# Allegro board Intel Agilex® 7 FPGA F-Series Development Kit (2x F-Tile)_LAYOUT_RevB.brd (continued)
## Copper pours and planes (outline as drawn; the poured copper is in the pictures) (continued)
FPGA_VCCPT on BOTTOM: 71.9,50.04 72.83,50.04 73,50.2 73,51.31 72.79,51.51 71.96,51.51 71.69,51.24 71.69,50.25
FPGA_VCCPT on L05_SIG2: 97.29,70.94 105.42,71.07 107.58,72.6 108.47,72.6 114.31,78.44 121.42,78.44 121.67,78.18 122.44,78.18 125.61,75.01 127.77,75.01 131.83,70.94 131.83,69.55 133.61,67.77 133.61,60.02 134.12,59.51 135.26,59.51 137.42,61.67 163.71,61.67 167.01,64.98 167.01,67.9 170.06,70.94 178.82,70.94 179.46,70.31 179.46,63.32 178.32,62.18 173.36,62.18 166.76,55.58 166.76,50.37 165.62,49.23 135.01,49.23 126.88,57.36 126.88,68.28 124.21,70.94 122.82,70.94 122.69,71.07 121.29,71.07 120.91,71.45 120.73,71.45 120.3,71.88 117.53,71.88 116.84,71.19 116.87,66.2 118.52,64.55 118.52,53.53 112.09,49.61 112,49.61 111.13,48.75 111.13,46.69 110.65,46.21 110.65,42.55 111.77,41.43 111.77,31.45 111.13,30.81 97.54,30.81 96.15,32.21 96.15,37.14 95.59,37.7 95.59,40.11 96.53,41.05 96.53,44.86 95.64,45.75 95.64,53.16 96.02,53.55 109.99,53.55 114.69,56.34 114.69,68.28 114.31,68.66 109.61,68.66 109.23,68.28 97.29,68.28 97.04,68.53 97.04,70.69
FPGA_VCCPT on L07_SIG3: 213.11,53.29 213.11,39.45 212.61,38.94 208.29,38.94 207.91,39.32 207.91,47.7 195.46,60.15 174,60.15 170.31,63.83 170.31,72.98 170.82,73.48 179.2,73.48 184.41,68.28 189.75,68.28 190.7,67.33 199.08,67.33
FPGA_VCCPT on L09_PWR1: 99.96,53.16 99.7,53.42 99.19,53.42 98.69,52.91 96.78,52.91 96.27,53.42 96.02,53.42 95.64,53.04 90.3,53.04 88.53,51.26 70.75,51.26 70.49,51.01 70.49,45.04 74.94,40.59 82.05,40.59 85.73,36.91 85.73,28.53 85.99,28.27 92.84,28.27 93.1,28.02 123.96,28.02 133.23,18.75 218.32,18.75 219.46,19.89 219.46,41.23 218.57,42.12 194.95,42.12 193.05,40.21 169.17,40.21 168.28,39.32 168.28,34.75 166.63,33.1 157.11,33.1 156.09,34.11 156.09,68.66 156.85,69.42 182,69.42 182.13,69.55 182.13,89.36 178.82,92.66 149.99,92.66 148.6,91.26 148.6,34.24 148.34,33.99 135.14,33.99 132.6,36.53 109.86,36.53 109.61,36.78 109.61,37.16 109.35,37.42 102.24,37.42 99.96,39.7
FPGA_VCCPT on L12_SIG4: 71.13,51.26 70.49,50.62 58.81,50.62 58.43,51.01 55.51,51.01 48.14,58.37 48.14,61.29 43.31,66.12 43.31,73.48 47.61,77.78 66.45,77.78 68.59,75.64 69.86,75.64 70.24,76.02 70.24,78.69 69.35,79.58 47.38,79.58 41.79,73.99 41.79,66.63 41.28,66.12 41.28,63.2 42.3,62.18 44.71,62.18 46.24,60.66 46.24,53.83 48.88,51.18 50.63,51.18 53.22,48.59 72.14,48.59 72.78,49.23 72.78,51.13 72.65,51.26
FPGA_VCCPT on L12_SIG4: 170.82,73.87 179.08,73.87 182.89,70.06 194.95,70.06 200.71,64.3 200.71,56.3 214.38,42.62 214.38,39.7 213.75,39.07 211.59,39.07 207.65,43 205.11,43 190.76,57.36 181.11,57.36 172.22,66.25 170.31,66.25 169.17,67.39 169.17,72.21
FPGA_VCCPT on L16_SIG6: 107.45,70.94 107.7,70.69 107.7,69.42 103,64.72 103,53.16 102.62,52.78 99.19,52.78 98.81,53.16 98.81,66.12 97.29,67.64 97.29,70.56 97.67,70.94
FPGA_VCCR_CORE on TOP (solid shape): 49.41,74.88 49.41,72.47 49.16,72.21 48.65,72.21 48.27,71.83 48.27,66.25 48.01,65.99 42.43,65.99 42.17,66.25 42.17,74.25 42.43,74.5 43.95,74.5 44.53,75.09 49.21,75.09
FPGA_VCCR_CORE on BOTTOM (solid shape): 47.63,74.12 47.63,71.83 47.51,71.71 47.51,68.02 47.63,67.9 47.63,66.5 47.38,66.25 42.17,66.25 41.66,66.75 41.66,71.2 42.68,72.21 42.68,74.25 42.81,74.37 47.38,74.37
FPGA_VCCR_CORE on TOP: 77.93,29.68 81.8,29.68 81.92,29.81 81.92,32.8 81.8,32.92 77.92,32.92 77.67,32.67 77.67,29.93
FPGA_VCCR_CORE on L09_PWR1: 63.25,28.27 84.84,28.27 85.35,28.78 85.35,36.65 81.92,40.08 74.94,40.08 70.11,44.91 70.11,51.01 69.86,51.26 59.44,51.26 55.63,55.07 55.63,64.85 53.98,66.5 53.98,81.61 53.6,81.99 39.38,81.99 39,81.61 39,76.02 35.57,72.6 35.57,55.96
FPGA_VCCR_CORE on L12_SIG4: 47.78,77.32 66.15,77.32 70.62,72.85 72.78,72.85 73.81,71.82 74.7,71.82 75.24,71.28 77.58,71.28 79.36,70.18 80.74,70.18 85.35,67.52 85.61,67.26 86.11,67.26 86.37,67.52 86.88,67.52 87.13,67.26 87.34,67.26 92.09,70.06 101.66,70.06 101.91,69.8 102.6,69.8 103.54,68.86 104.81,68.86 105.75,69.8 106.18,69.8 106.43,70.06 109.1,70.06 109.35,69.8 109.35,66.57 105.42,64.41 105.42,56.21 106.94,54.69 107.32,54.69 107.83,54.18 107.83,50.75 104.91,47.83 87,47.83 86.11,46.94 83.32,46.94 82.94,46.56 80.78,46.56 80.65,46.69 79.76,46.69 79.51,46.43 76.21,46.43 74.43,48.21 74.05,48.21 73.16,49.1 73.16,51.26 72.78,51.64 71,51.64 70.37,51.01 59.06,51.01 58.55,51.51 55.63,51.51 48.65,58.5 48.65,61.55 43.7,66.5 43.7,73.23
LTC_VDD33 on TOP: 233.94,28.65 231.27,28.65 231.02,28.91 231.02,30.43 231.27,30.69 233.94,30.69 234.2,30.43 234.2,28.91
LTC_VDD33 on BOTTOM: 172.22,57.99 170.95,57.99 170.7,58.24 170.7,62.44 170.95,62.69 179.59,62.69 179.84,62.44 179.84,60.66 179.59,60.4 176.28,60.4 176.03,60.66 175.39,60.66 174.76,61.29 172.73,61.29 172.47,61.04 172.47,58.24
LTC_VDD33 on L16_SIG6: 196.22,38.43 195.33,39.32 195.33,42.88 194.57,43.64 188.6,43.64 185.94,46.31 185.94,48.85 186.19,49.1 186.57,49.1 187.08,48.59 187.08,47.45 187.59,47.45 187.84,47.7 187.84,52.02 184.28,55.58 184.28,58.75 181.24,61.8 172.22,61.8 171.33,60.91 171.33,54.05 178.06,47.32 178.06,42.37 189.75,30.69 212.86,30.69 217.43,26.11 234.32,26.11 235.08,26.88 235.08,30.81 234.32,31.57 222,31.57 215.15,38.43
MAX_1V2 on BOTTOM (solid shape): 17.68,70.99 18.6,70.99 18.8,70.79 18.8,65.61 17.41,64.21 16.71,64.21 16.63,64.23 15.9,64.23 15.9,64.47 16.62,64.47 16.62,64.75 15.89,64.75 15.89,65.36 16.39,65.86 16.39,70.46 17.1,70.46 17.1,70.84 16.72,70.84 16.72,70.46 16.39,70.46 16.39,71.2 17.48,71.2
MAX_1V2 on BOTTOM: 20.71,85.68 20.71,84.53 20.84,84.41 21.34,84.41 21.44,84.51 21.44,85.78 20.81,85.78
MAX_1V2 on L16_SIG6: 16.01,67.26 16.01,81.61 19.44,85.04 20.45,85.04 21.09,85.68 27.06,85.68 29.73,83.01 29.73,76.28 30.49,75.52 31.25,75.52 31.63,75.14 31.63,73.48 31.12,72.98 26.17,72.98 25.41,72.21 25.41,70.94 21.11,66.65 16.62,66.65
MAX_1V8 on BOTTOM (solid shape): 33.64,101.8 33.68,101.79 34.31,101.79 34.41,101.69 34.41,101.55 33.69,101.55 33.69,101.27 34.42,101.27 34.42,99.78 35.44,98.76 35.44,94.57 35.31,94.44 34.04,94.44 33.79,94.69 33.79,98 32.9,98.88 32.9,100.81 32.94,100.81 33.17,100.93 33.26,101.16 33.23,101.3 33.15,101.42 33.53,101.81 33.6,101.81
MAX_1V8 on BOTTOM: 25.41,55.07 27.19,55.07 28.07,54.18 28.07,52.15 27.95,52.02 27.06,52.02 26.93,52.15 26.93,53.16 26.55,53.55 25.41,53.55 ; 1 cut-out
MAX_1V8 on L03_SIG1: 34.63,95.2 36.74,95.2 37.5,95.96 38.11,95.96 38.12,95.95 38.2,95.95 39.35,97.11 42.17,97.11 42.68,97.61 67.01,97.61 67.19,97.44 67.19,95.33 64.88,93.02 64.88,83.11 69.53,78.46 72.6,78.46 72.88,78.74 72.88,79.58 72.55,79.91 70.54,79.91 66.66,83.8 66.66,92.05 69.53,94.92 69.53,98.88 67.85,100.56 43.19,100.56 42.15,99.52 39.05,99.52 36.6,97.07 35.02,97.07 34.49,96.54 34.49,95.34
MAX_1V8 on L09_PWR1: 38.49,94.19 35.82,96.85 32.9,96.85 29.85,93.8 23.76,93.8 22.74,92.79 22.74,85.42 22.87,85.3 23.38,85.3 24.65,86.57 28.33,86.57 29.34,85.55 29.34,82.88 27.44,80.98 27.19,80.98 26.93,80.72 26.93,80.09 26.55,79.71 25.79,79.71 25.41,80.09 25.41,80.72 25.03,81.1 23.88,81.1 23.38,80.6 23.38,76.66 21.72,75.01 21.72,73.61 22.87,72.47 29.98,72.47 30.49,71.96 30.49,62.56 29.22,61.29 17.15,61.29 16.9,61.04 16.9,56.34 19.82,53.42 29.73,53.42 32.39,56.09 34.93,56.09 35.19,56.34 35.19,72.85 38.49,76.15
MAX_2V5 on TOP (solid shape): 33.92,99.9 33.92,98.88 34.3,98.5 34.3,94.57 34.04,94.31 33.15,94.31 32.9,94.57 32.9,98.38 32.39,98.88 32.39,99.75 33.13,99.75 33.13,100.03 32.39,100.03 32.39,100.15 32.51,100.27 33.14,100.27 33.17,100.27 33.22,100.28 33.54,100.28
MAX_2V5 on BOTTOM: 32.77,94.31 33.28,94.31 33.54,94.57 33.54,96.73 33.28,96.98 32.77,96.98 32.52,96.73 32.52,94.57
MAX_2V5 on L10_PWR2: 38.49,94.19 35.82,96.85 32.9,96.85 29.85,93.8 23.76,93.8 22.74,92.79 22.74,85.42 22.87,85.3 23.38,85.3 24.65,86.57 28.33,86.57 29.34,85.55 29.34,82.88 27.44,80.98 27.19,80.98 26.93,80.72 26.93,80.09 26.55,79.71 25.79,79.71 25.41,80.09 25.41,80.72 25.03,81.1 23.88,81.1 23.38,80.6 23.38,76.66 21.72,75.01 21.72,73.61 22.87,72.47 33.15,72.47 35.06,74.37 35.06,75.77 38.49,79.2
MAX_VCCD on L03_SIG1: 22.08,85.45 25.51,85.45 26.68,84.28 31.38,84.28 31.76,83.9 31.76,79.33 31.5,79.07 30.11,79.07 29.73,78.69 29.73,72.72 30.23,72.21 31.25,72.21 31.63,71.83 31.63,69.29 31.25,68.91 20.84,68.91 20.45,69.29 20.45,83.82
PCIE_3V3_AUX on TOP: 54.35,5.8 53.98,6.17 53.98,8.46 54.24,8.71 54.87,8.71 55.13,8.46 55.13,5.92 54.95,5.75 54.95,2.6 54.35,2.6
PCIE_3V3_AUX on BOTTOM: 54.24,7.19 54.87,7.19 55.13,7.44 55.13,8.84 55,8.97 54.11,8.97 53.98,8.84 53.98,7.44
PCIE_3V3_AUX on L16_SIG6: 54.62,5.67 52.08,5.67 44.03,13.72 38.18,13.72 33.99,17.91 33.99,26.16 34.07,26.24 34.55,26.24 35.47,25.33 39.66,25.33 47.06,17.92 47.06,14.49 47.76,13.79 51.89,13.79 53.51,12.18 55.2,12.18 56.02,11.36 56.02,9.01 55.43,8.42 55.43,6.48
PCIE_EP_3V3 on TOP: 52.35,2.6 52.35,5.77 52.08,6.05 52.08,8.59 52.2,8.71 53.22,8.71 53.35,8.59 53.35,6.17 52.95,5.78 52.95,2.6
PCIE_EP_3V3 on BOTTOM: 53.35,2.6 53.35,5.66 52.08,6.94 52.08,8.77 52.25,8.94 53.5,8.94 53.73,8.71 53.73,7.32 54.95,6.09 54.95,2.6
PCIE_EP_3V3 on L03_SIG1: 54.87,11.51 54.87,10.75 53.86,9.73 53.86,6.3 53.6,6.05 52.08,6.05 51.82,6.3 51.82,9.73 51.19,10.37 49.54,10.37 49.16,10.75 49.16,11.51 49.54,11.89 54.49,11.89
PCIE_EP_12V on TOP: 45.65,6 45.65,8.89 46.08,9.32 48.65,9.32 48.93,9.05 48.93,6.96 48.7,6.73 48.52,6.73 48.22,6.43 48.22,5.92 47.95,5.66 47.95,2.6 45.45,2.6 45.45,5.79
PCIE_EP_12V on TOP: 226.96,44.02 226.58,43.64 220.48,43.64 220.1,43.26 220.1,31.83 220.61,31.32 226.58,31.32 227.21,31.96 227.21,39.45 227.08,39.58 227.08,40.22 226.93,40.38 226.93,41.33 227.08,41.48 227.08,44.02 ; 1 cut-out
PCIE_EP_12V on BOTTOM: 219.97,31.32 226.96,31.32 227.21,31.57 227.21,40.72 226.96,40.97 226.96,43.39 226.7,43.64 219.97,43.64 219.72,43.39 219.72,31.57
PCIE_EP_12V on BOTTOM: 46.35,2.6 46.35,5.8 46.11,6.05 46.11,8.82 46.26,8.97 48.52,8.97 48.65,8.84 48.65,6.81 48.22,6.38 48.22,5.92 47.95,5.66 47.95,2.6
PCIE_EP_12V on L09_PWR1: 46.27,5.92 46.27,10.92 46.26,11.16 46.24,11.4 46.24,11.51 49.79,15.06 62.49,15.06 65.67,11.89 121.29,11.89 124.59,15.19 129.67,15.19 132.47,17.99 138.06,17.99 138.44,17.99 218.7,17.99 220.23,19.51 220.23,43.13 220.86,43.77 228.23,43.77 228.73,43.26 228.73,15.06 227.72,14.05 169.93,14.05 169.93,14.02 140.78,14.02 138.64,13.14 137.76,11 137.76,10.26 130.66,10.26 128.8,9.48 128.03,7.62 128.03,6.3 59.37,6.3 59.37,7.45 57.15,9.67 54.93,7.45 54.93,6.17 54.55,5.79 46.4,5.79
PCIE_EP_12V on L10_PWR2: 46.27,5.92 46.27,10.92 46.26,11.16 46.24,11.4 46.24,11.51 49.79,15.06 62.49,15.06 65.67,11.89 121.29,11.89 124.59,15.19 129.67,15.19 132.47,17.99 218.7,17.99 220.23,19.51 220.23,43.13 220.86,43.77 228.23,43.77 228.73,43.26 228.73,15.06 227.72,14.05 169.93,14.05 169.93,14.02 140.78,14.02 138.64,13.14 137.76,11 137.76,10.26 130.66,10.26 128.8,9.48 128.03,7.62 128.03,6.3 59.37,6.3 59.37,7.45 57.15,9.67 54.93,7.45 54.93,6.17 54.55,5.79 46.4,5.79
PCIE_VDD_1V85 on TOP (solid shape): 231.02,46.31 230.39,46.31 229.88,45.8 229.88,45.42 229.75,45.29 229.12,45.29 228.99,45.42 228.99,45.8 230.26,47.07 230.26,47.7 230.39,47.83 231.02,47.83
QSFP_VCC on BOTTOM (solid shape): outline of 922 points within 36.99,49.1 48.75,58.27
QSFP_VCCR on BOTTOM (solid shape): outline of 100 points within 36.99,47.27 45.5,49.46
QSFP_VCCT on BOTTOM (solid shape): outline of 828 points within 36.98,40.31 48.7,48.82
QSFPDD_VCC on BOTTOM (solid shape): outline of 236 points within 48.14,27.41 58.81,35.28
QSFPDD_VCCR on BOTTOM (solid shape): 49.43,27.7 49.66,27.47 52.52,27.47 52.84,27.16 52.84,26.39 52.59,26.14 48.01,26.14 48.01,29.33 48.05,29.33 48.05,31.58 49.43,31.58
QSFPDD_VCCT on BOTTOM (solid shape): outline of 168 points within 48.06,22.3 59.32,27.03
SW0 on TOP: 153.42,41.73 153.3,41.61 153.3,40.08 153.42,39.96 154.82,39.96 155.07,39.7 155.07,36.65 155,36.58 150.2,36.58 149.41,37.37 149.41,44.33 150.22,45.14 154.97,45.14 155.07,45.04 155.07,41.73
SW1 on TOP: 153.42,27.13 153.3,27 153.3,25.48 153.42,25.35 154.82,25.35 155.07,25.1 155.07,22.18 154.95,22.05 149.84,22.05 149.41,22.48 149.41,30.18 149.77,30.53 154.97,30.53 155.07,30.43 155.07,27.13
SW2 on TOP: 153.42,56.21 153.3,56.09 153.3,54.56 153.42,54.43 154.82,54.43 155.07,54.18 155.07,51.13 155,51.06 150.12,51.06 149.41,51.77 149.41,58.88 150.15,59.62 154.97,59.62 155.07,59.51 155.07,56.21
SW3 on TOP: 153.42,70.69 153.3,70.56 153.3,69.04 153.42,68.91 154.57,68.91 154.82,68.66 154.82,65.61 154.74,65.53 150.12,65.53 149.41,66.25 149.41,73.36 150.15,74.09 154.97,74.09 155.07,73.99 155.07,70.69
SW4 on TOP: 153.42,85.17 153.3,85.04 153.3,83.52 153.42,83.39 154.82,83.39 155.07,83.14 155.07,80.09 155,80.01 150.12,80.01 149.41,80.72 149.41,87.84 150.15,88.57 154.97,88.57 155.07,88.47 155.07,85.17
U93_AGND on TOP (solid shape): outline of 824 points within 39.38,87.58 52.2,94.06
U93_AGND on BOTTOM (solid shape): outline of 252 points within 38.74,75.42 51.44,94.57
U93_AGND on TOP: 51.72,89.08 51.72,89.99 51.59,90.12 48.22,90.12 48.09,89.99 48.09,89.03 48.22,88.9 48.5,88.9 48.8,88.6 48.8,88.22 48.9,88.12 49.13,88.12 49.21,88.19 49.21,88.6 49.51,88.9 51.54,88.9
U93_AGND on L14_SIG5: 51.34,89.39 51.34,91.85 52.2,92.71 52.2,93.3 51.82,93.68 47.38,93.68 46.74,93.04 46.24,93.04 45.6,92.41 45.6,91.8 43.54,89.74 42.35,89.74 41.87,89.26 39.94,89.26 39.55,88.88 39.55,87.68 39.83,87.4 46.67,87.4 48.32,89.06 51.01,89.06
U93_VDD25 on L03_SIG1: 39.22,92.33 39.22,89.06 39.53,88.75 41.31,88.75 42.35,89.79 42.35,92.23 41.61,92.97 39.86,92.97
U93_VDD25 on L05_SIG2: 46.87,93.93 42.04,93.93 41.03,92.92 41.03,89.99 43.95,87.07 47.51,87.07 48.14,87.71 48.14,88.72 47.63,89.23 47.63,93.17
U93_VDD33 on L03_SIG1: 43.82,93.68 46.95,93.68 47.3,93.32 47.3,91.57 47.48,91.39 48.78,91.39 49.11,91.06 49.11,90.17 49.79,89.49 49.79,87.71 49.41,87.33 42.09,87.33 41.64,87.79 41.64,88.5 43.2,90.06 43.2,93.06
U96_AGND on TOP (solid shape): outline of 813 points within 195.23,75.52 201.81,88.72
U96_AGND on TOP: 196.83,76.38 197.75,76.38 197.87,76.51 197.87,79.89 197.75,80.01 196.78,80.01 196.65,79.89 196.65,79.61 196.35,79.3 195.97,79.3 195.87,79.2 195.87,78.97 195.94,78.9 196.35,78.9 196.65,78.59 196.65,76.56
U96_AGND on BOTTOM: 196.93,79.13 197.05,79.01 197.05,76.66 197.49,76.66 197.75,76.91 197.75,79.62 197.58,79.78 195.29,79.78 195.02,80.06 195.02,83.33 195.33,83.64 195.33,84.41 195.46,84.53 201.56,84.53 201.68,84.41 201.68,79.45 201.81,79.33 202.06,79.33 202.32,79.58 202.32,88.6 201.43,89.49 187.97,89.49 187.33,90.12 183.75,90.12 183.65,90.02 183.65,89.23 183.67,89.21 183.67,88.29 184.08,87.89 193.89,87.89 194.32,87.45 194.32,84.41 193.94,84.03 193.94,80.18 194.99,79.13 ; 2 cut-outs
U96_VDD25 on L16_SIG6: 202.06,88.47 202.06,85.68 201.68,85.3 199.4,85.3 199.02,84.91 199.02,83.77 197.75,82.5 197.75,80.09 197.37,79.71 195.46,79.71 195.08,80.09 195.08,83.39 196.48,84.79 196.48,88.47 196.86,88.85 201.68,88.85
U96_VDD33 on L16_SIG6: 198.13,82.25 198.13,79.83 197.62,79.33 195.21,79.33 194.7,79.83 194.7,83.64 196.1,85.04 196.1,86.44 195.71,86.82 193.17,86.82 192.79,86.44 192.79,76.66 193.05,76.41 200.92,76.41 202.06,77.55 202.06,84.53 201.68,84.91 199.78,84.91 199.4,84.53 199.4,83.52
ZL30733_1V8 on TOP (solid shape): 69.22,64.47 69.22,63.45 66.68,63.45 66.18,62.95 65,62.95 65,63.68 64.78,63.68 64.78,63.07 64.54,63.07 64.54,63.69 64.53,63.72 64.52,63.77 64.52,64.34 64.65,64.47 66.05,64.47 66.3,64.72 68.97,64.72
ZL30733_1V8 on BOTTOM (solid shape): outline of 243 points within 59.19,58.75 72.02,65.48
ZL30733_1V8 on BOTTOM: 57.54,43.77 57.54,44.78 55.23,44.78 55.05,44.61 55.05,43.39 55.18,43.26 55.63,43.26 56.14,43.77
ZL30733_1V8 on L14_SIG5: 58.6,60.66 60.71,60.66 60.97,60.4 60.97,59.72 60.38,59.13 60.38,46.87 56.65,43.13 55.25,43.13 55.18,43.21 55.18,43.87 57.54,46.23 57.54,46.74 58.33,47.53 58.33,60.38
N93250 on BOTTOM: 52.11,94.82 52.11,99.16 51.9,99.37 49.97,99.37 49.82,99.22 49.82,94.82 49.99,94.64 50.66,94.64 50.84,94.82
N632203 on L16_SIG6: 6.61,55.83 6.61,47.58 6.87,47.32 13.6,47.32 13.85,47.58 13.85,55.83 13.6,56.09 6.87,56.09
N632667 on L07_SIG3: 12.71,52.28 12.71,50.37 12.45,50.12 2.67,50.12 2.42,50.37 2.42,52.28 2.67,52.53 12.45,52.53
N757891 on TOP: 246.74,109.43 247.83,109.96 249.03,110.14 251.86,108.97 253.03,106.14 253.02,105.87 252.99,105.6 252.99,99.9 252.77,99.36 252.23,99.14 251.47,99.14 251.2,99.03 251.09,98.76 251.09,96.98 251.2,96.71 251.47,96.6 252.23,96.6 252.77,96.38 252.99,95.84 252.99,16.99 253,16.82 253.01,16.65 252.73,15.18 251.93,13.92 246.08,13.92 245.28,15.18 245,16.65 246.18,19.48 249.01,20.65 250.43,20.39 251.67,19.64 252.1,19.64 252.37,19.75 252.48,20.02 252.48,95.71 252.37,95.98 252.1,96.09 251.34,96.09 250.8,96.31 250.58,96.85 250.58,98.88 250.8,99.42 251.34,99.65 252.1,99.65 252.37,99.76 252.48,100.03 252.48,102.44 252.37,102.71 252.1,102.82 251.26,102.82 251.05,102.69 250.84,102.58 249.96,102.25 249.03,102.14 247.77,102.34 246.64,102.93 245.03,106.14 246.64,109.35 246.64,109.43
N757891 on BOTTOM: 246.74,109.43 247.83,109.96 249.03,110.14 251.86,108.97 253.03,106.14 253.02,105.87 252.99,105.6 252.99,99.9 252.77,99.36 252.23,99.14 251.47,99.14 251.2,99.03 251.09,98.76 251.09,96.98 251.2,96.71 251.47,96.6 252.23,96.6 252.77,96.38 252.99,95.84 252.99,16.99 253,16.82 253.01,16.65 252.73,15.18 251.93,13.92 246.08,13.92 245.28,15.18 245,16.65 246.18,19.48 249.01,20.65 250.43,20.39 251.67,19.64 252.1,19.64 252.37,19.75 252.48,20.02 252.48,95.71 252.37,95.98 252.1,96.09 251.34,96.09 250.8,96.31 250.58,96.85 250.58,98.88 250.8,99.42 251.34,99.65 252.1,99.65 252.37,99.76 252.48,100.03 252.48,102.19 252.33,102.55 251.98,102.69 251.06,102.69 250.08,102.28 249.03,102.14 246.7,102.89 245.24,104.85 242.96,104.85 242.83,104.98 242.83,108.92 243.34,109.43 ; 3 cut-outs
N1703797 on BOTTOM: 71.25,44.91 71.51,44.66 72.78,44.66 72.91,44.78 72.91,48.59 71.41,50.09 71.41,54.36 71.28,54.49 70.77,54.49 70.65,54.36 70.65,48.03 70.8,47.88 71.05,47.88 71.25,47.68 ; 2 cut-outs
N2608710 on TOP: 240.62,25.53 240.62,27.97 240.09,28.5 238.21,28.5 236.13,26.42 231.32,26.42 231.02,26.11 231.02,24.46 231.27,24.21 239.3,24.21
N2975570 on BOTTOM: 52.11,102.44 52.11,106.78 51.9,106.99 49.97,106.99 49.82,106.84 49.82,105.74 50.55,105.01 50.55,104.22 49.82,103.49 49.82,102.39 49.97,102.24 50.98,102.24 51.19,102.44
N6231213 on TOP (solid shape): 50.12,82.04 50.12,79.91 49.54,79.33 49.54,77.19 49.41,77.07 44.51,77.07 44.51,81.87 44.76,82.12 50.05,82.12
N6231502 on TOP (solid shape): 56.09,80.77 56.09,77.07 51.32,77.07 51.19,77.19 51.19,79.2 50.48,79.91 50.48,82.04 50.55,82.12 54.74,82.12
N6646840 on TOP (solid shape): 189.87,77.55 189.87,72.6 189.36,72.09 184.03,72.09 183.78,72.34 183.78,76.36 183.78,76.66 184.03,76.91 186.72,76.91 187.43,77.63 189.8,77.63
N6648304 on TOP (solid shape): 189.87,84.41 189.87,78.06 189.75,77.93 187.46,77.93 186.82,78.56 183.78,78.56 183.61,78.73 183.61,84.49 184.03,84.91 189.36,84.91
N6731924 on TOP: 71.76,42.24 72.57,42.24 72.57,38.35 72.14,37.92 66.05,37.92 65.03,36.91 65.03,35 63.76,35 63.76,38.69 64.52,39.45 71,39.45 71.76,40.21 ; 10 cut-outs
N8086837 on BOTTOM: 223.91,64.85 223.91,66.88 223.53,67.26 220.61,67.26 220.48,67.13 220.48,66.25 220.61,66.12 222.38,66.12 222.89,65.61 222.89,64.85

Small or netless copper shapes (teardrops, artwork), in the pictures only: 97 on TOP, 35 on BOTTOM

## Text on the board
BOTTOM: 100-0330678-B1 RevB1 | BOTTOM SIDE LAYER 18
User.Comments: CR_111111_33 | CR_111111_31 | CR_111111_29 | CR_111111_28 | CR_UNNAMED_68 | CR_111111_30 | CR_111111_22 | CR_1_6 | CR_123_1 | CR_111111_18 | CR_111111_19 | CR_UNNAMED_45 | CR_111111_24 | CR_111111_17 | CR_111111_25 | CR_111111_23 | CR_111111_27 | CR_111111_21 | CR_111111_26 | CR_111111_20 | CR_UNNAMED_27 | CR_U34_2 | CR_UNNAMED_48 | CR_UNNAMED_38 | CR_111111_1 | CR_UNNAMED_31 | CR_UNNAMED_32 | CR_UNNAMED_28 | CR_UNNAMED_36 | CR_111111_2 | CR_111111_3 | CR_111111_4 | CR_U32_2 | CR_U32_1 | CR_4444_1 | CR_11_2 | CR_UNNAMED_56 | CR_UNNAMED_49 | CR_UNNAMED_23 | CR_Q4_3 | CR_U69_1 | CR_U17_1 | CR_654321_5 | CR_Q4_2 | CR_UNNAMED_30 | CR_UNNAMED_26 | CR_654321_4 | CR_123456_19 | CR_123456_52 | CR_123456_54 | CR_123456_8 | CR_1123_2 | CR_123456_56 | CR_123456_17 | CR_1111111_2 | CR_1111111_4 | CR_1111111_5 | CR_1111111_7 | CR_Q4_5 | CR_1111111_6 | CR_UNNAMED_74 | CR_1111111_9 | CR_1111111_10 | CR_1111111_1 | CR_123456_39 | CR_UNNAMED_53 | CR_UNNAMED_63 | CR_111111_32 | CR_41_2 | CR_41_3 | CR_123456_40 | CR_111111_59 | CR_111111_58 | CR_111111_55 | CR_111111_56 | CR_111111_57 | CR_111111_54 | CR_1111_2 | CR_111111_10 | CR_111111_11 | CR_111111_9 | CR_111111_12 | CR_111111_5 | CR_UNNAMED_77 | CR_UNNAMED_78 | CR_UNNAMED_79 | CR_111111_6 | CR_111111_8 | CR_111111_7 | CR_111111_35 | CR_111111_36 | CR_444444_2 | CR_UNNAMED_69 | CR_Q4_4 | CR_Q4_6 | MEZZANINE MODULE | NOTES: UNLESS OTHERWISE SPECIFIED | 1.  ASSEMBLY BOARD PER IPC-A-610 (LATEST REVISION) STANDARD. | 2.  HANDLE MOISTURE SENSITIVE DEVICES(MSD) PER MANUFACTURE'S | CALL OUT ON MSD LABEL.  IF MSD LABEL IS MISSING OR NOT LEGIBLE | 3.  USE IPC-7711/7721 (LATEST REVISION) FOR ALL PCBA REWORK. | THEN ALL PLASTIC PACKAGED COMPONENTS ARE TO BE CONSIDERED MSD | LEVEL 6 AND USE EIA/JEP 113-A FOR HANDLING.
TOP: TOP SIDE LAYER 1
Ref Des/Silkscreen Top: EXTERNAL JTAG | TCK | TDO | TMS | TDI | CFG1 | CFG0 | IMG_SEL1 | D12:FPGA_CONF_DONE | D5:OVERTEMP | QSFP | 1 | 2 | D1:MAX_CONF_DONE | D2:POWER GOOD | IMG_SEL0 | QSFPDD | LTC7132 PROG | MAX10_JTAG_EN | CPU_RESETn | HPS_RESETN | Config Mode | AS x4 Norm | AS x4 Fast | AVST x16 | JTAG | (CVP) | PCIE_PERSTn | GXF_2ND_PERSTN | MSEL2 | 0 | CXL_PERSTn | MSEL1 | SW3 | MSEL0 | 3 | CLOSE-->SELECT | OPEN-->DESELECT | CLOSE=0 | OPEN=1 | MAX_I2C | USB_MAX_JTAG_SEL | CLOSED=0.5% DOWN SPREAD | LTC3888 PROG | OPEN=NO SREAD SPECTRUM | SW4.1 | SW4.2 TO SW4.4 | OPEN=HIGH | PCIE PRESENT | CLOSED=LOW | X16 | X4 | X8 | X1 | SCL | 1_PPS_SCOPE1 | POWER_ON | SDA | 1_PPS_SCOPE2 | CXL | A | DDR4 DIMM 2 | DDR4 DIMM 1 | HPS_GPIO | USER LEDS | INPUT POWER | FAN | Agilex F-Series FPGA Development Kit, Two F-Tile Edition | 2LI
DIMENSION: 3X | 59.6 | 0.1339 | 0.0340 | 0.0551 | 0.0681 | 0.1585 | 0.2521 | 3.40 | 0.86 | 1.40 | 1.73 | 4.03 | 6.40 | 45 X.0200 | 45 X0.51 | 2X | 3.65 | 0.1437 | 1.9 | .0748 | 2.74 | .1080 | 3.51 | .1380
PAGE_OUTLINE: THIS DOCUMENT CONTAINS PROPRIETARY INFORMATION | OF INTEL CORP. NEITHER THE DOCUMENT NOR SAID | PROPRIETARY INFORMATION SHALL BE PUBLISHED, | REPRODUCED, COPIED, DISCLOSED OR USED FOR ANY | PURPOSE OTHER THAN CONSIDERATION OF THIS DOCUMENT | WITHOUT THE EXPRESS WRITTEN PERMISSION OF A DULY | AUTHORIZED REPRESENTATIVE OF INTEL CORPORATION | PROPRIETARY NOTICE: | R | REV | B1
DISPLAY_BOTTOM: P8 | P37 | P46 | P55 | P64 | P27 | P9 | P26 | P38 | P47 | P56 | P65 | P28-29 | P39 | P48 | P57 | P66 | P10 | P23 | P67 | P11 | P30 | P40 | P49 | P58 | P42 | P12-21 | P31 | P41 | P50 | P59 | P22 | P32 | P51 | P60 | P33 | P43 | P52 | P61 | P34 | P35 | P44 | P53 | P62 | P45 | P36 | P54 | P63
User.22: INTERNAL SIGNAL LAYER 3
User.23: INTERNAL GND PLANE LAYER 2
User.25: PRIMARY SIDE PASTE MASK
User.26: SECONDARY SIDE PASTE MASK
User.27: PRIMARY SIDE SILKSCREEN
User.28: SECONDARY SIDE SILKSCREEN
User.29: PRIMARY SIDE SOLDERMASK
User.30: SECONDARY SIDE SOLDERMASK
User.31: INTERNAL PWR PLANE LAYER 10
User.32: INTERNAL GND PLANE LAYER 11
User.33: INTERNAL SIGNAL LAYER 12
User.34: INTERNAL GND PLANE LAYER 13
User.35: INTERNAL SIGNAL LAYER 14
User.36: INTERNAL GND PLANE LAYER 15
User.37: INTERNAL SIGNAL LAYER 16
User.38: INTERNAL GND PLANE LAYER 17
User.39: INTERNAL XXX LAYER 18
User.40: INTERNAL XXX LAYER 19
User.41: INTERNAL XXX LAYER 20
User.42: INTERNAL XXX LAYER 21
User.43: INTERNAL XXX LAYER 22
User.44: INTERNAL XXX LAYER 23
User.45: C1221 | C1220 | C1224 | C1228 | C1225 | C1226 | R6898 | R6945 | R6944 | R6890 | C1018 | R6887 | R6903 | R6888 | C1019 | C1021 | R6883 | R6855 | C1020 | R6818 | R6811 | R6807 | R6829 | R6809 | C1178 | R6839 | C1215 | C1214 | C1179 | C1203 | C1191 | C1156 | C1193 | R6853 | R6852 | C1217 | C1180 | R6868 | R6940 | R747 | R6941 | R6942 | R6943 | R6837 | C1125 | R6880 | C1009 | C1008 | C1011 | C1010 | C1124 | C1123 | R869 | R118 | R117 | R6934 | R6910 | R6935 | R6923 | R6924 | C1121 | R6843 | R6842 | R6931 | R6930 | R6933 | R756 | R755 | R6925 | R6926 | R6928 | R6927 | R6936 | R6937 | R6921 | R6922 | R6886 | R6863 | C1120 | C1026 | C1098 | R6849 | C1080 | C1205 | C1127 | R6834 | C1206 | R6833 | R6835 | R6794 | R6791 | R6799 | R6798 | R1008 | R6797 | R6845 | R6846 | R6844 | R6847 | R6848 | R6895 | C1001 | C1000 | R6907 | R6906 | C1024 | C1022 | C1025 | C1023 | C1264 | R115 | R6917 | R116 | R6929 | R6908 | C1056 | C1060 | C1061 | C1237 | C1051 | R6920 | R6915 | R6913 | R6810 | C1269 | C1274 | C1273 | C1271 | C1285 | C1260 | C1275 | C1270 | C1272 | C1286 | C1263 | C1268 | C1287 | C1267 | C1284 | R6900 | R6899 | C1288 | C1289 | C1261 | C1277 | C1278 | C1279 | C1262 | C1276 | C1281 | C1280 | C1229 | C1230 | C1231 | C1232 | C1234 | C1219 | C1235 | C1236 | C1227 | C1233 | C1223 | R6889 | C1003 | R6904 | R6905 | R6884 | R6814 | R6830 | R665 | R6832 | R6808 | R6813 | R6831 | R6867 | R6821 | R6812 | C1158 | R6828 | C1093 | C1204 | R6873 | R6819 | R6875 | R6874 | R6815 | R6876 | R6825 | R6822 | R6896 | C1157 | R6851 | C1103 | C1028 | C1200 | C1027 | C1165 | C1164 | R6838 | C1030 | C1029 | C1197 | C1194 | C1196 | C1031 | C1195 | R1004 | C1126 | R6918 | C1073 | C1053 | R6871 | R6872 | C1049 | R6859 | R6860 | R6870 | R6869 | R6939 | R6938 | R6857 | R6858 | C1050 | R6919 | R6916 | R6909 | R6911 | R6932 | R6897 | C1199 | R6865 | R6885 | R6862 | R6861 | C1222 | C1201 | C1202 | R6877 | R6881 | R6850 | R6882 | C1081 | C1213 | C1209 | C1211 | C1149 | C1212 | C1082 | C1210 | R6836 | C1207 | R1007 | R6894 | R6893 | R6892 | R6891 | R6878 | R6879 | C1002 | R6840 | R6841 | C1052 | R1005 | C1218 | C1283 | C1266 | C1265 | C1282 | R6912 | R124 | C1057 | C1042 | C1043 | C1058 | C1062 | C1068 | C1059 | C1067 | C1066 | C1054 | C1055 | C1064 | C1069 | C1063 | C1065 | C1070 | C1071 | R128 | R6914 | R1 | R3 | R4 | R2 | R533 | R534 | R532 | R541 | C1038 | C1040 | C1039 | C1041 | R103 | Q24 | Q23 | Q3 | R765 | R740 | R98 | R97 | R306 | R304 | R302 | R466 | R465 | R464 | R102 | R101 | R100 | R99 | R307 | R308 | R309 | U47 | R426 | C349 | C350 | R225 | R226 | C342 | C343 | R404 | R93 | C340 | C341 | C347 | C348 | R405 | R406 | R407 | R456 | R458 | C601 | C603 | R472 | R475 | C623 | C648 | C487 | R438 | R431 | R437 | R436 | R430 | R435 | R429 | R825 | R824 | R823 | R822 | C653 | C485 | R815 | R816 | R817 | R818 | C483 | R848 | R849 | R808 | R358 | 1 | C482 | R203 | R204 | R814 | R821 | R820 | R819 | R205 | C867 | R5 | R402 | R403 | R7 | R8 | C922 | ST30 | R866 | R241 | R256 | R257 | R264 | R263 | R240 | R246 | R262 | R261 | R245 | R244 | R260 | R259 | R243 | R258 | C1216 | R843 | R864 | R863 | R842 | C1198 | R743 | R746 | C945 | C450 | R725 | C931 | R748 | C977 | R742 | C983 | R745 | C452 | C946 | R724 | C963 | R750 | R400 | R401 | R722 | R344 | R342 | C951 | C949 | C950 | C954 | C955 | R749 | C1046 | C1045 | C1077 | ST34 | R739 | R265 | C541 | C101 | R12 | R642 | C1078 | C1076 | C19 | R774 | R15 | C701 | ST7 | R643 | R152 | R136 | R153 | R137 | R546 | R545 | C1079 | C1034 | R359 | R346 | R347 | R348 | R349 | R737 | ST11 | ST10 | ST9 | ST8 | ST14 | C461 | C460 | R596 | R588 | R580 | R572 | R604 | C459 | C537 | C518 | C538 | C534 | R727 | R718 | C539 | C1032 | C521 | R154 | R138 | C1033 | R119 | R841 | C232 | C242 | C207 | C199 | C221 | C211 | C209 | C1035 | C1075 | C1074 | C212 | C219 | C200 | C229 | C217 | C224 | C197 | C239 | R151 | C230 | C236 | C205 | C203 | C233 | C237 | C213 | C189 | C190 | C159 | C156 | C179 | C194 | C145 | C153 | C220 | R716 | C929 | C241 | C202 | C231 | C210 | C225 | C198 | C228 | R720 | C278 | C265 | C254 | C246 | C280 | C513 | C251 | C252 | C528 | C255 | R155 | R139 | C267 | C245 | C277 | C263 | C271 | C243 | R156 | R140 | C281 | C773 | C756 | C755 | C738 | C737 | C723 | C719 | C702 | C791 | C775 | C510 | C276 | C285 | C258 | C248 | C284 | C283 | R594 | R591 | R592 | R595 | R586 | R583 | R584 | R587 | R578 | R575 | R576 | R579 | R570 | R567 | R568 | R571 | R602 | R599 | R600 | R603 | C256 | C456 | C286 | C287 | C249 | C275 | C259 | C270 | C244 | C273 | C272 | C111 | C108 | R197 | R184 | R187 | R189 | R172 | R194 | R543 | R547 | C783 | R544 | C765 | C729 | C711 | C747 | C966 | C971 | C973 | C969 | R190 | R183 | R180 | R170 | R168 | R201 | R192 | R178 | R171 | R167 | R169 | C696 | R191 | R845 | C110 | C972 | C121 | R195 | C970 | C291 | C968 | R385 | R196 | R383 | R384 | R376 | R377 | R763 | R738 | C974 | R182 | R186 | C289 | R188 | R174 | R531 | C693 | R757 | R758 | C352 | C375 | C690 | C374 | C373 | C372 | R95 | R764 | R96 | R759 | R760 | C376 | R555 | R553 | R552 | R551 | R550 | R554 | R542 | R535 | R560 | R536 | R538 | R539 | C958 | C362 | R380 | R379 | R378 | R382 | R381 | C472 | R609 | C932 | C930 | R343 | R620 | R728 | R614 | R744 | R644 | R741 | C936 | C926 | R127 | R126 | C107 | R123 | C444 | R327 | C371 | C368 | R239 | C361 | C359 | FB13 | C409 | FB42 | C380 | R328 | C923 | C921 | R645 | C1092 | R326 | C320 | C925 | R125 | R840 | R839 | C915 | C364 | C449 | R332 | R1006 | C187 | C152 | R852 | R331 | C191 | C157 | R333 | C335 | C327 | C315 | C316 | R334 | R217 | R218 | C868 | C866 | R215 | R637 | R858 | R27 | C869 | R470 | C864 | R857 | R785 | R784 | C649 | R214 | C92 | R434 | R80 | R77 | R78 | R76 | R42 | R58 | C295 | C302 | C326 | C325 | C664 | R769 | R39 | C49 | R32 | C657 | C658 | C656 | R54 | C68 | C80 | R79 | R43 | R59 | R72 | R57 | R41 | C299 | R29 | R26 | R444 | R440 | R439 | R443 | C50 | C81 | R770 | C654 | C652 | R38 | C93 | C85 | C61 | R504 | R494 | C621 | C622 | R478 | R474 | R471 | R479 | R477 | R476 | R442 | R74 | C55 | C489 | R223 | R37 | C51 | R34 | C57 | C626 | R433 | R432 | C56 | C606 | C602 | C620 | C48 | C598 | R789 | C625 | C629 | C53 | C60 | C100 | C99 | FB29 | R311 | R310 | C435 | R313 | R312 | C436 | R315 | R317 | R220 | R771 | R36 | C79 | C87 | C491 | C599 | C600 | R459 | R461 | R462 | R455 | R457 | R460 | C97 | C71 | FB1 | C503 | R525 | R527 | R526 | R523 | R530 | C421 | C993 | C420 | C997 | C995 | C422 | C52 | C662 | C660 | C661 | FB28 | R529 | C497 | R297 | R296 | R294 | R292 | R325 | R324 | R323 | R322 | R320 | R321 | C499 | C498 | C665 | C650 | C501 | FB27 | C412 | FB40 | C989 | C991 | R274 | R272 | C416 | C990 | C988 | FB39 | R473 | C624 | C98 | C410 | C490 | C411 | R450 | C492 | R453 | C417 | C413 | FB37 | R837 | R836 | R834 | R833 | C418 | C414 | FB38 | C992 | R266 | R267 | R275 | R273 | R285 | R284 | R282 | R283 | R287 | R286 | C115 | R109 | C562 | C549 | R108 | C571 | C550 | R762 | C94 | C91 | U48 | C607 | Q22 | Q21 | D11 | D10 | D9 | D8 | C494 | C493 | R454 | C495 | FB30 | C608 | R766 | R463 | R767 | R847 | R480 | R428 | C486 | C663 | R427 | R500 | R497 | C609 | R469 | C651 | R422 | R425 | R468 | R777 | R418 | C303 | ST1 | ST2 | R663 | R667 | R209 | R208 | R207 | R210 | R206 | R664 | R90 | R87 | R714 | R712 | R704 | R713 | C1154 | R862 | R711 | R709 | R242 | R13 | R370 | R865 | C16 | R254 | C466 | C467 | R6802 | R717 | R238 | R253 | R20 | R366 | R369 | C388 | C27 | R367 | R368 | C981 | C987 | C387 | R337 | R248 | C961 | C956 | R338 | C390 | R247 | R339 | R726 | C389 | R250 | C940 | R341 | C396 | R249 | C453 | C944 | C939 | C980 | C976 | C986 | C982 | C393 | R252 | C392 | R251 | C985 | ST31 | C391 | R234 | R237 | R236 | R235 | R229 | R228 | R231 | R230 | R232 | R233 | R107 | R641 | R161 | R145 | C28 | C195 | C162 | C193 | C158 | R21 | C196 | C161 | FB2 | C109 | C536 | C533 | C457 | C458 | C766 | C748 | C730 | C712 | C784 | R351 | R353 | R598 | R597 | R590 | R589 | R582 | R581 | R574 | R573 | R606 | R605 | C762 | C742 | C722 | C708 | C774 | C767 | C749 | C731 | C713 | C785 | C29 | R22 | C126 | C535 | C540 | C519 | C524 | C1037 | C1044 | C1036 | C30 | R23 | C520 | R163 | C240 | C166 | C134 | C23 | C238 | C168 | C132 | C47 | R150 | R134 | R18 | C215 | C216 | C46 | C188 | C155 | C186 | C154 | C201 | C222 | C184 | C133 | C167 | C150 | C206 | C45 | C227 | C44 | C185 | C143 | C177 | C151 | R135 | C43 | C42 | R164 | C234 | C235 | C934 | C41 | C40 | C935 | C214 | C218 | C927 | C933 | C204 | C223 | C208 | C39 | C176 | C140 | C38 | C226 | C525 | C552 | C175 | C141 | C173 | C139 | C122 | C36 | C937 | C169 | C137 | C35 | C171 | C135 | R165 | C279 | C172 | C142 | C266 | C174 | C138 | R159 | R143 | C34 | C33 | C512 | C526 | C527 | C260 | C262 | C572 | C548 | C573 | C170 | C136 | C545 | C247 | C269 | C128 | R157 | R141 | C32 | C253 | R158 | R142 | C546 | C511 | C529 | C31 | C274 | C25 | C127 | R19 | R352 | R110 | C26 | C24 | R345 | C763 | C745 | C727 | C709 | C781 | R166 | C764 | C746 | C728 | C710 | C782 | C282 | C288 | R593 | R585 | R577 | R569 | R601 | C20 | C261 | C264 | C18 | C250 | C268 | R761 | C257 | C15 | C14 | R104 | R199 | C13 | C12 | C290 | R549 | R175 | R173 | R17 | C700 | R181 | C967 | C22 | C698 | R16 | R564 | R202 | C293 | R177 | C21 | R565 | R200 | R566 | R198 | C292 | C11 | R193 | R548 | C10 | R561 | C120 | C975 | C473 | R179 | R562 | C699 | R176 | C697 | R563 | C470 | C119 | C9 | R556 | C118 | FB5 | FB12 | C117 | C8 | R558 | C694 | FB18 | R559 | C116 | R537 | C351 | R557 | C957 | C691 | C386 | C948 | R540 | C7 | C367 | C928 | FB22 | C6 | C960 | FB21 | C947 | C978 | C394 | C385 | R715 | C984 | C943 | C941 | C395 | C379 | C397 | C384 | R719 | R14 | C979 | FB23 | C399 | C378 | C959 | FB19 | C17 | R340 | C471 | C398 | C377 | C400 | C401 | C365 | C942 | FB15 | C2 | R868 | C451 | FB24 | C1 | C402 | C360 | C366 | C953 | C404 | C356 | C403 | R729 | C405 | C357 | FB14 | FB25 | C952 | C407 | C353 | R723 | C938 | C358 | C920 | C406 | C408 | C355 | R721 | C962 | FB26 | R706 | C354 | C317 | R708 | C309 | C383 | C318 | R6 | C369 | C363 | C382 | C1208 | C310 | C370 | FB17 | FB16 | FB20 | C297 | C381 | C311 | C298 | C301 | C312 | C313 | C319 | C300 | C314 | SW2 | C865 | R666 | R668 | SW6 | R855 | R854 | C308 | C307 | C331 | R28 | R213 | R212 | C332 | C328 | C337 | C37 | R395 | C334 | C330 | C338 | R82 | ST20 | R394 | C333 | C329 | C336 | R786 | R399 | C346 | R33 | R780 | C488 | C305 | C304 | C70 | C82 | C306 | R773 | R211 | R30 | R24 | R25 | R31 | R40 | R772 | R495 | R467 | R222 | R221 | R56 | R105 | R501 | R505 | R498 | R73 | R106 | C655 | C689 | C90 | C66 | C89 | R85 | C95 | C96 | C344 | C78 | C345 | C627 | C75 | C72 | C54 | C86 | R528 | R411 | C323 | C628 | R441 | R55 | C59 | C69 | R524 | R507 | C322 | R35 | R81 | R75 | C324 | R445 | C77 | C65 | R522 | R503 | C605 | R71 | R293 | C423 | R52 | C73 | C58 | C604 | R70 | R295 | C996 | R299 | C64 | C62 | R69 | R290 | R447 | R298 | R768 | C63 | ST32 | C432 | R291 | R446 | R301 | C83 | C88 | ST33 | C84 | C994 | R300 | R449 | R319 | R91 | R89 | R92 | R84 | C424 | R303 | R318 | C496 | R53 | C659 | R288 | R86 | C433 | C502 | R305 | R448 | R499 | C999 | R289 | R83 | R316 | C67 | C76 | C74 | R88 | R502 | R314 | R398 | C998 | R94 | R506 | C434 | R496 | C500 | R452 | R451 | R281 | R279 | R269 | R271 | R754 | R280 | R219 | R753 | R278 | C415 | R224 | R227 | R277 | R276 | R268 | R270 | R856 | C577 | R114 | C114 | C587 | C586 | C585 | C584 | C543 | C582 | C583 | C561 | C1047 | C1048 | C544 | C530 | C551 | C575 | C542 | C574 | C576 | C1072 | C112 | C579 | C578 | C113 | Max component height bottom side | of PCIe card: .105/2.67mm | COUT20 | COUT14 | C1250 | C1252 | COUT8 | C1253 | C1255 | C1249 | C1238 | C1239 | C1240 | C1241 | C1242 | C1243 | C1244 | C1245 | C1246 | C1247 | C1248 | C1257 | C1256 | C1259 | U87 | U88 | D4 | D7 | D3 | D6 | C580 | C591 | C588 | C589 | C581 | C590 | C517 | COUT25 | COUT27 | COUT28 | COUT26 | COUT30 | COUT29 | COUT17 | COUT18 | COUT21 | COUT22 | COUT23 | COUT24 | COUT9 | COUT10 | COUT11 | COUT12 | COUT15 | COUT16 | COUT1 | COUT2 | COUT3 | COUT4 | COUT5 | COUT6 | COUT33 | COUT34 | COUT35 | COUT36 | COUT37 | C515 | COUT32 | COUT39 | COUT31 | COUT19 | COUT13 | COUT7 | C508 | C505 | C506 | C507 | C509 | FB11 | FB10 | U90 | U89 | C1258 | C1254 | C1251 | U28 | U31 | Q2 | D25 | D12 | D24 | D5 | D2 | D1 | FB41 | FB8 | FB6 | C514 | C516 | C522 | C523 | C504 | FB4 | U12 | U91 | D20 | D21 | Q7 | Q12 | Q13 | Q14 | D18 | D19 | B1 | C1174 | C771 | C744 | C726 | C707 | C1136 | C1146 | Y2 | C688 | C1144 | C1142 | C1145 | C1143 | C1135 | C1134 | C1096 | C1133 | C1132 | C1099 | C1101 | C1176 | C1115 | C1189 | C1118 | C192 | C160 | C770 | C759 | C752 | C741 | C734 | C724 | C716 | C705 | C788 | C769 | C768 | C758 | C757 | C751 | C750 | C740 | C739 | C733 | C732 | C721 | C720 | C715 | C714 | C704 | C703 | C787 | C786 | C777 | C776 | C779 | C181 | C183 | C147 | C149 | C178 | C144 | C180 | C146 | C761 | C753 | C735 | C717 | C778 | C182 | C148 | C772 | C760 | C754 | C743 | C736 | C725 | C718 | C706 | C790 | C789 | C780 | C1117 | U39 | U38 | C1116 | C1160 | C1159 | C1100 | C1102 | C1162 | C1161 | C1128 | C1097 | C1129 | R148 | R147 | R132 | R131 | L3 | L2 | L1 | C1138 | C1139 | FB9 | C597 | C596 | C594 | C618 | C619 | C595 | Q20 | Q19 | C1086 | C1084 | C296 | C1085 | C1087 | C1106 | C1107 | C1112 | C1110 | C1111 | C1182 | C1181 | C1167 | C1166 | C1185 | C1186 | C1172 | C1170 | C1187 | C1188 | C1173 | C1171 | FB3 | C1105 | U36 | C1122 | C1091 | D17 | C339 | A37 | A1 | B37 | C484 | C617 | C616 | D26 | J106 | J105 | C123 | D27 | U60 | Q10 | Q15 | Q11 | Y1 | Q17 | C614 | C125 | C124 | C321 | D28 | U56 | U51 | D22 | D23 | U80 | U81 | EU1 | U78 | U10 | EU2 | U76 | U77 | U75 | U74 | U70 | U20 | U53 | U57 | U21 | Q1 | Q4 | U58 | D16 | U52 | Q9 | Q8 | U6 | DWG NO. | SIZE | SCALE: 1/1 | REV | CAGE CODE | SHEET 2 OF 2 | FB7 | PROPRIETARY NOTICE: | THIS DOCUMENT CONTAINS PROPRIETARY INFORMATION | OF ALTERA CORP. NEITHER THE DOCUMENT NOR SAID | PROPRIETARY INFORMATION SHALL BE PUBLISHED, | REPRODUCED, COPIED, DISCLOSED OR USED FOR ANY | PURPOSE OTHER THAN CONSIDERATION OF THIS DOCUMENT | WITHOUT THE EXPRESS WRITTEN PERMISSION OF A DULY | AUTHORIZED REPRESENTATIVE OF ALTERA CORPORATION | DEC .XXXX  .002 | 01 | INTEL CONFIDENTIAL | 3065 BOWERS AVE | SANTA CLARA | CALIF.  95051 | MTH8 | MTH1 | U7 | D13 | D15 | Q18 | U24 | MTH3 | MTH9 | J1 | MTH10 | MTH5 | L12 | S1 | S2 | Q16 | C592 | S3 | U44 | S4 | S6 | C593 | MTH11 | C695 | SW5 | MTH7 | MTH2 | J12 | J10 | SW3 | SW4 | SW1 | BT1 | R417 | X1 | X2 | D14 | NOTES:(UNLESS OTHERWISE SPECIFIED) | (USE FOR OSP ONLY ) | 19. VIA PLUGGING REQUIREMENTS FOR TEST PAD VIA (EXCEPTION IS NOTE 23): | THE VIAS THAT ARE USED AS TEST PADS ARE REQUIRED TO BE PLUGGED ON THE SIDE THAT | IS OPPOSITE TO THE TEST PADS. THE PLUGGED MATERIAL HAS TO BE FILLED AT LEAST 40% | AND NO MORE THAN 90% OF THE VIA HEIGHT MEASURED FROM THE SIDE OPPOSITE TO THE TEST | PADS. IT IS REQUIRED THAT AIR SHALL NOT FLOW THROUGH FROM ONE END OF THE TEST PAD | VIA TO THE OTHER. THERE IS NO CONTINUOUS AIR GAP FROM ONE END TO THE OTHER END | OF THE VIA. THEY ARE REQUIRED TO BE STUFFED 3 TIMES AS FOLLOWS: | a. STUFF SOLDERMASK INTO THE VIAS FROM THE SIDE OPPOSITE THE TEST PADS. | b. SEAL THE VIAS USING SOLDERMASK ON THE SIDE OPPOSITE OF THE TEST PADS. | c. SEAL THE VIAS USING SOLDERMASK ON THE TEST PAD SIDE. | d. MAKE SURE THE SOLDERMASK IS TOTALLY CLEANED FROM ALL TEST PADS DURING | THE SOLDERMASK CLEANING PROCESS. | (IMPEDANCES SUBJECT TO CHANGE PER PROJECT REQUIREMENTS) | 20. REQUIRED REPORT OF PRODUCTION BOARDS: | EVERY 3 OR LESS LOTS AND 5000 OR LESS BOARDS, THE FOLLOWING TESTS ARE REQUIRED | BEFORE THE BOARDS ARE SHIPPED OUT. A COPY OF THE REPORT AND IMPEDANCE COUPON | TO BE SENT TO THE ENGINEER INVOLVED. | a. MEASURE THE FOLLOWING IMPEDANCES OF 30 RANDOMLY PICKED BOARDS: | i. SEE IMEPACNE TABLE FOR REQUIRED IMPEDANCES AND LAYERS TO BE MEASURED. | b. MEASURE THE Tg OF A PIECE OF MATERIAL FROM THE BOARD PANEL. THE Tg VALUE | HAS TO BE GREATER THAN .145. | c. CROSS SECTION A TEST PAD VIA FROM EACH CORNER OF ONE PCB (4 TEST PADS VIAS TOTAL). | THEY HAVE TO BE PICKED FROM TEST PAD VIAS THAT ARE CLOSE TO EACH CORNER. | PICTURES OF THE CROSS SECTION SHOWING THE STUFFING ARE REQUIRED | IN THE REPORT. MEASURE THE PERCENTAGE OF THE STUFFING IN THE PLUGGED VIAS, | COPPER FOIL + PLATING THICKNESS (TOP TO BOTTOM), COPPER PLATING | THICKNESS IN HOLE (6 LOCATIONS - 2 TOPS, 2 MIDDLES AND 2 BOTTOMS), | DIELECTRIC THICKNESS (CENTER AND CORNER), | TRACE PROPERTY (TOP WIDTH, BANDWIDTH AND THICKNESS), AND BOARD THICKNESS (WITHOUT SOLDERMASK). | d. MEASURE ALSO THE FOLLOWING ITEMS FROM ONE BOARD: | i .   OSP THICKNESS | i i . BOW AND TWIST (MAX AND MIN ) | i i i PEEL STRENGTH | iv.   CLEANLINESS TEST | v.    SOLDERABILITY | v i . THERMAL STRESS | vii.  THE DIMENSIONS OF ONE OF EVERY KIND OF HOLE | viii. THE OUTER DIMENSIONS OF THE BOARD | 1. MATERIALS: MEG*6. | 2. THIS DRAWING ALSO EXISTS ON ELECTRONIC MEDIA. | 3. FABRICATE PWB PER IPC-6012 CLASS 2 (LATEST REVISION). | 4. DIMENSIONING AND TOLERANCING PER ANSI Y14.5M. | 5. BOARD MUST BE UL 94V-0 APPROVED. | 6. BREAKOUT IN THE REGION OF THE TRACE/PAD JUNCTION SHALL NOT REDUCE THE | TRACE WIDTH BY MORE THAN 25% UNLESS OTHERWISE SPECIFIED. | 7. COPPER IN HOLES SHALL BE PER I PC - 6012(LATEST REVISION), CLASS 2. | 8. MAXIMUM BOARD WARPAGE IN ANY DIRECTION TO BE ,0075'/INCH, AS MEASURED BY | IPC-TM-650 TEST METHOD 2.4.22. | 9. VENDOR MARKING: VENDOR LOGO, UL MARKING AND DATECODE (4DIGIT WWYY)TO BE IN | ETCH ON SECONDARY (BOTTOM) SIDE AWAY FROM ALL BOARD FEATURES. | 10. FEATURE SIZE TOLERANCE: PLATED THRU HOLE PADS, INTERNAL PLANE CLEARANCES | (ANTIPADS) AND SURFACE MOUNT LAND PATTERNS SHALL BE +/- 10% OF THEIR CAD | DIMENSION WITH THE FOLLOWING EXCEPTION. ANY SMT LAND PATTERNS THAT HAVE | A FINISHED PAD WIDTH OR DIAMETER LESS THAN OR EQUAL TO .012' MUST USE THE | FOLLOWING TOLERANCE, +/-.001'. PCB VENDOR TO ADJUST ARTWORK TO | COMPENSATE FOR ETCH PROCESS. NOTE: THIS APPLIES TO ETCH SIZES BEFORE SOLDERMASK. | FURTHERMORE, FOR ETCH COMPENSATION, ONLY MINIMAL AMOUNT IS ALLOWED. | NO GEOMETRIES MAY BE ENLARGED FOR YIELD PURPOSES. | FINISHED PRODUCT MUST MATCH INTEL CAD DATA AS CLOSE AS POSSIBLE. | 11. FEATURE LOCATION TOLERANCE: ALL CONDUCTIVE FEATURES SHALL BE WITHIN | .008' DIAMETER TRUE POSITION REGARDLESS OF FEATURE SIZE (RFS). | 12. HOLE LOCATION TOLERANCE: PLATED THRU HOLES SHALL BE WITHIN .003' DIAMETER | TRUE POSITION AT MAXIMUM MATERIAL CONDITION (MMC ) . NON-PLATED HOLES <.200" | SHALL BE WITHIN .003' DIAMETER TRUE POSITION WITH RESPECT TO 0,0 DATUM. | NON-PLATED HOLES >.200 SHALL BE WITHIN .003' DIAMETER TRUE POSITION WITH | RESPECT TO DATUM. | 13. SILKSCREEN BOTH SIDES USING NON - CONDUCTIVE INK. COLOR: WHITE. | NO SILKSCREEN SHALL BE ON ANY EXPOSED COPPER PAD. TRIMMING ALLOWED EVEN | IF IMPACT TO LEGIBILITY. | 14. REMOVE ALL UNUSED PADS FROM INNER LAYERS. | 15. IMPEDANCE TO BE VERIFIED PER TABLE. IMPEDANCE COUPONS MUST REFLECT EACH | CONTROLLED IMPEDANCE FOR EACH LAYER. MEASUREMENTS MUST BE PERFORMED BY TDR. | IMPEDANCE REPORTING MUST SPECIFY EACH CONTROLLED IMPEDANCE GEOMETRY BY LAYER. | FULL AND ACCURATE REPORTING AND COUPONS MUST BE PROVIDED WITH BOARDS. RECORDS | MUST BE MAINTAINED BY SUPPLIER FOR REFERENCE BY DESIGN TEAM AS REQUIRED. | REPORTS PER LOT INFORMATION PER DATE CODE MUST BE AVAILABLE UPON REQUEST. | 16. SURFACE FINISH: ENIG (ENTHONE HT PLUS,FORMOCHEM F35,SHIKOKU F2 (LX) PLUX | THICKNESS SHALL BE 0.25 TO 0.50 MICRON). | 17. VIAS THAT ARE MASKED OVER BY DESIGN ARE PLUGGED, 30% TO 90%. VIAS WITH | SOLDERMASK OPENINGS ON TOP SIDE ARE BY DESIGN AND REMAIN OPEN. | EXCEPTION IS NOTE 23 | 18. SOLDERMASK BOTH SIDES, USING GREEN MATTE OR GLOSS SOLDERMASK PER I PC-SM-840. | SOLDERMASK PADS SHALL BE ENLARGED BY .004" OVERALL OR .002' PER SIDE | INCLUDING SOLDERMASK DEFINED PADS. SOLDERMASK DEFINED PADS SHALL STRICTLY FOLLOW | .002' OVERSIZE PER SIDE. NOTE 22 IS THE EXCEPTION. | NO CHANGE ALLOWED WITHOUT INTEL APPROVAL. | 25. ADD COPPER THIEVING WHERE NECESSARY, AND MAINTAIN A CLEARANCES OF 35 MILS TO ALL NETS. | 26. REMOVE THE THROUGH HOLE VIA PAD ON BOTTOM LAYER FOR THE PCIE GEN5 TO EDGE FINGER, | CXL TO MCIO  CONNECTOR AND QSFP-DD SIGNALS ROUTED ON LAYER16. | 27. IN EDGE FINGER REGION, SOME RESIDUAL METAL FROM THE PLATING TIE BAR IS PERMITTED TO | EXTEND NO MORE THAN 0.13 MM BEYOND THE BOTTOM OF THE EDGE FINGERS, INTO THE METAL | EXCLUSION REGION (BETWEEN THE EDGE FINGER AND CHAMFER REGION), "ETCH BACK" PROCESS | MAYBE REQUIRED TO DO THIS. | 21. EDGE CONNECTOR FINGERS:REQUIRE 30 MICRO INCHES HARD GOLD OVER 150-200 | MICRO INCHES OF NICKEL. | 22. FOR BGA "U2", ALL EXPOSED COPPER PADS, WHETHER SMD OR NSMD, MUST HAVE A 20 MILS PAD DIAMETER, | THEY ALL MUST BE EQUAL. | 23. FILL ALL 8MIL, 10MIL AND 12MIL DRILL HOLES USING NON - CONDUCTIVE EPOXY | 24. PLEASE ADD TEAR DROPS TO OUTER AND INNER LAYERS. | AND OVERPLATE WITH COPPER (VIPPO). | *** SPECIAL NOTES*** | 1. INNER LAYER IMPEDANCE IS +/-7% (BOTH FOR MASS AND SAMPLE PRODUCTION) | 2. OUYER LAYER IMPEDANCE IS +/-10% (BOTH FOR MASS AND SAMPLE PRODUCTION) | 3. THROUGH HOLE VIA 8MILS DRILL : FINISHED HOLE WITH EPOXY AND PLATED SHUT ALMOST 6MIL | 4. MICRO VIA 1-2, VIA 1-3, & 16-18, 17-18 : 10 MIL DRILL; FILLED MICRO-VIA WITH EPOXY. | Impedance | Layer | 3 | 5 | 7 | 12 | 14 | 16 | 18 | - MUST NOT CUT LAYER 16 | IMPEDANCE TABLE (SEE SPECIAL NOTE) | NOTES: | - MNC_LAYER: MUST-NOT-CUT-LAYER | - MAX_DEPTH: DEPTH FROM START LAYER TO THE | SURFACE OF MUST-NOT-CUT-LAYER | - MFG_STUB : MANUFACTURING STUB LENGTH | INTERNAL GND PLANE LAYER 4 | INTERNAL GND PLANE LAYER 6 | INTERNAL GND PLANE LAYER 8 | INTERNAL PWR PLANE LAYER 9 | INTERNAL SIGNAL LAYER 5 | INTERNAL SIGNAL LAYER 7 | INTERNAL XXX LAYER 24 | INTERNAL XXX LAYER 25 | INTERNAL XXX LAYER 26 | INTERNAL XXX LAYER 27 | INTERNAL XXX LAYER 28 | INTERNAL XXX LAYER 29 | INTERNAL XXX LAYER 30 | PRESS FIT | BACKDRILL DIAMETER | (D2=D1+8mils) | .050 CENTERS TYP. | BACKDRILL: L18 to L16 | THRU VIA 1-18 | MICRO VIA 16-18 | MICRO VIA 17-18 | .100 TABS TYP. | .025 NPTH TYP (3 PLCS) | .100 TYP. | L10/PLN - 1.0 Oz Cu | L11/PLN - 1.0 Oz Cu | L13/PLN - 0.5 Oz Cu | L14/SIG - 0.5 Oz Cu | L15/PLN - 0.5 Oz Cu | L16/SIG - 0.5 Oz Cu | L17/PLN - 0.5 Oz Cu | L18/BOT - 0.5 Oz Cu | L01/TOP - 0.5 Oz Cu 0.6 MILS THK | L12/SIG - 0.5 Oz Cu | L02/PLN - 0.5 Oz Cu | L03/SIG - 0.5 Oz Cu | L04/PLN - 0.5 Oz Cu | L05/SIG - 0.5 Oz Cu | L06/PLN - 0.5 Oz Cu | L07/SIG - 0.5 Oz Cu | L08/PLN - 1.0 Oz Cu | L09/PLN - 1.0 Oz Cu | MICRO VIA 1-2 | MICRO VIA 1-3 | 1078 Core  - 3 MILS THK | 1035 Core  - 2 MILS THK | Pre-1035HRC -2.3 MILS THK | COPPER PLATE 1.4MILS THK | Pre-1035HRC -2.7 MILS THK | Pre-1078LRC -2.7 MILS THK | Pre-1027/1035HRC -4.0 MILS THK | CHAMFER EDGE CONNECTOR | 1.3 MILS THK | SCALE: NONE | 0.6 MILS THK | 0.6MILS THK | 20.0 +/-2 | .051+/-.005 | 1.30+/-0.13 | SEE STACKUP | FOIL | LPHTE | HVLP | J3 | FIGURE | 42.5 OHM | (MILS) | 6.70 | 3.60 | 3.80 | 5.85 | 3.20 | 3.50 | 45 OHM | FINISHED_SIZE | 10.0 | 85 OHMS | Width/SP | 4.55/4.95 | 3.35/4.65 | 3.55/4.45 | DRILL CHART: TOP to L03_SIG1 | ALL UNITS ARE IN MILS | DRILL CHART: TOP to L02_GND1 | 3.20/4.00 | 3.50/4.00 | TOLERANCE_DRILL | +0.0/-10.0 | BD_SIZE | 16.0 | DETAIL "B" | 90 OHMS | 4.00/5.00 | 3.10/5.90 | 3.35/5.65 | PLATED | MNC_LAYER | L17_GND8 | BACKDRILL: BOTTOM to BOTTOM | 3.00/4.00 | NECKDOWN | QTY | 210 | 17 | TOOLING HOLE SIZE/LOCATION DETERMINED BY FAB VENDOR (4 PLCS) | MAX_DEPTH | 4.7 | 3.20/4.50 | MTH6 | MFG_STUB | - | 96 | C692 | MTH4 | 8.0 | 12.0 | 20.0 | 31.0 | 36.0 | 40.0 | 41.339 | 43.0 | 45.0 | 47.0 | 63.0 | 71.0 | 97.0 | 125.0 | 181.102 | 44.0 | 49.0 | 61.0 | 62.0 | 118.0 | 33.46x25.59 | 51.181x23.622 | 59.0x20.0 | 97.0x48.0 | U2 | U22 | U45 | U97 | U46 | DRILL CHART: L16_SIG6 to BOTTOM | DRILL CHART: L17_GND8 to BOTTOM | DRILL CHART: TOP to BOTTOM | +0.0/-8.0 | +0.0/-12.0 | +3.0/-3.0 | +1.969/-1.969 | +5.0/-0.0 | +2.0/-2.0 | J2 | U25 | J14 | J15 | NON-PLATED | 33 | 28 | 5823 | 674 | 1317 | 375 | 6 | 8 | 24 | 4 | 10 | 2 | Thickness After plating | (not including solder mask) | .0622 inch  +/-.005 | J107 | J13 | + | 100-0321309-01 | DETAIL | (CROSS SECTION) | L11 | L10 | U33 | U94 | U50 | U54 | U26 | U27 | C615 | U3 | U4 | L8 | L7 | L6 | L5 | L9 | L13 | AGILEX F-SERIES FPGA DEVKIT | J9 | U49 | J4 | J5 | U61 | U65 | U64 | U63 | U62 | U66 | PRIMARY SIDE SHOWN | SECONDARY SIDE SHOWN | BOTTOM SIDE SHOWN | TOP SIDE SHOWN | U23 | U19 | U18 | U17 | U16 | U15 | U96 | U9 | J11 | U93 | D | N/A | U95 | B | A | B2 | U5 | J8 | J7 | U8 | J6
